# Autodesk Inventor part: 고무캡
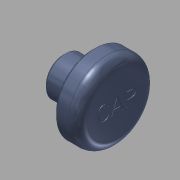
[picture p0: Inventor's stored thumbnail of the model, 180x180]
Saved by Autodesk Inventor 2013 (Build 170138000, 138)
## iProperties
Created: 2017-06
Part Number: 고무캡
Material: 고무
Document SubType Name: Modeling
Designer: mduedu
Density: 1 g/cm^3
Author: mduedu
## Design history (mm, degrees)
sketch "스케치1"
  geometry: L1 (0, 0)-(11, 0); L2 (11, 0)-(11, 8); L3 (11, 8)-(6.5, 8); L4 (0, 4)-(0, 0); L5 (0, 4)-(6, 4); L6 (6, 4)-(6, 7.5); L7 (6, 7.5)-(6.5, 7.5); L8 (6.5, 7.5)-(6.5, 8)
  constraints: 16 end point, 2 horizontal, 2 parallel, 2 perpendicular, 2 point on line, 1 vertical
  dimensions: "d0" = 16 diameter of L3 L1; "d2" = 8 diameter of L5 L1; "d6" = 5 distance between parallel lines of L2 L6; "d7" = 0.5 distance between parallel lines of L8 L6; "d8" = 15 diameter of L7 L1; "d9" = 6 distance between parallel lines of L6 L4
revolve "회전1" sketch "스케치1" stored, may be unused: angle "d10" = 90 deg
hole "구멍1" diameter "d22" = 5; stored, may be unused: countersink angle "d26" = 90 deg, drill point angle "d28" = 0 deg; dims "d23" = 6, "d24" = 4, "d25" = 2, "d27" = 6, "d30" = 10, "d31" = 10
chamfer "모따기1" distance "d13" = 0.5; stored, may be unused: second distance "d14" = 2, angle "d15" = 45 deg
fillet "모깎기3" dims "d29" = 1
fillet "모깎기1" dims "d16" = 0.1
fillet "모깎기2" dims "d17" = 2
sketch "스케치3"
  geometry: 2 further points
  constraints: 1 coincident, 1 other
feature "엠보싱1" sketch "스케치3" dims "d18" = 0.2, "d19" = 0
node "솔리드1"
